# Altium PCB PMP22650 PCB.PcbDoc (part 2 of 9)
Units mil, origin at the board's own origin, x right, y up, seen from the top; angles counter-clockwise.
Board outline 11311 x 5233 mil, 8 copper layers (Layer 1, Layer 2, Layer 3, Layer 4, Layer 5, Layer 6, Layer 7, Layer 8), stack 88.6 mil thick; 633 components, 410 nets, 2503 pads, 1993 vias.
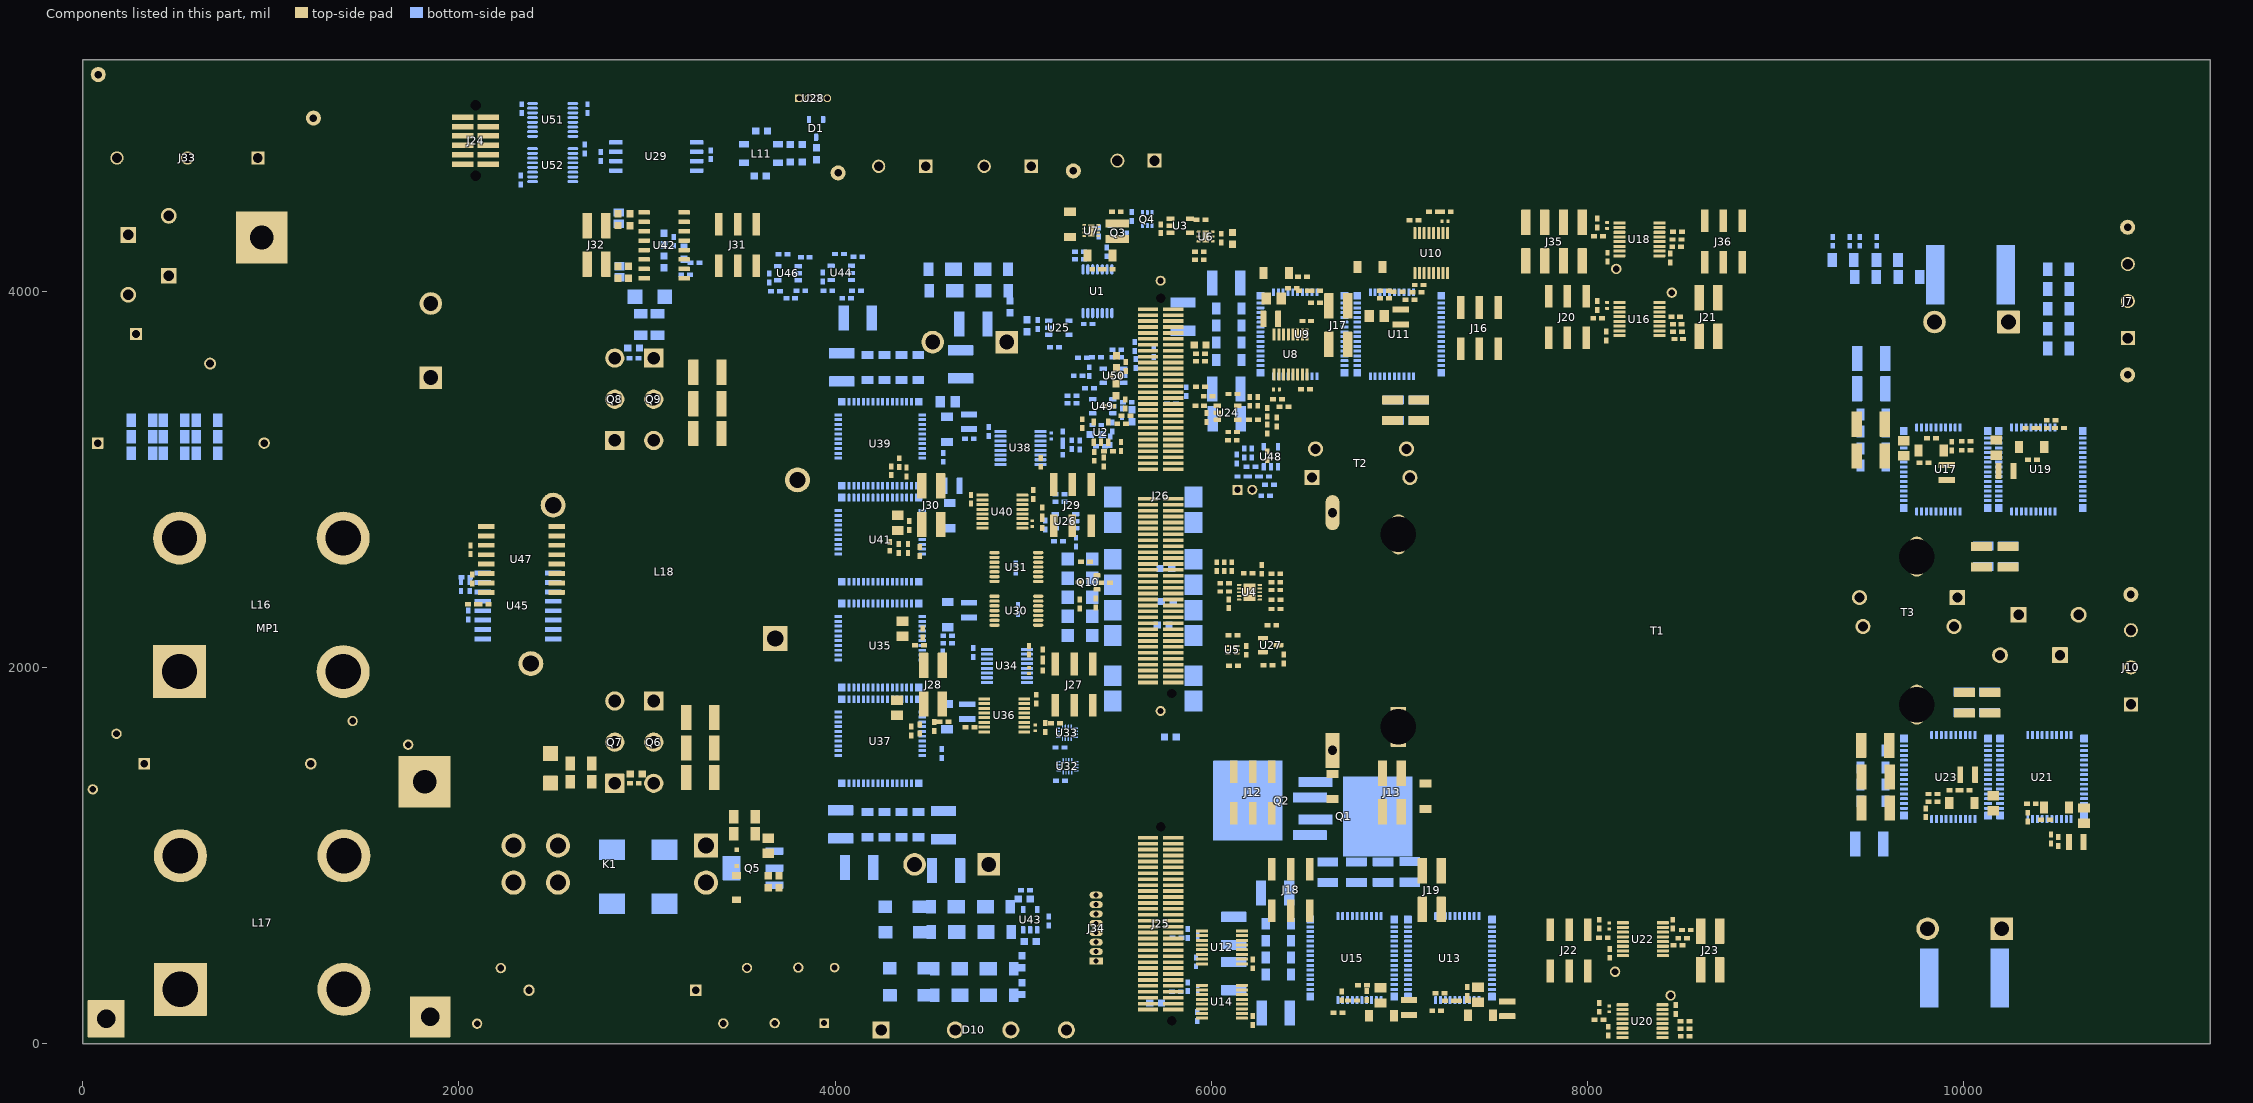
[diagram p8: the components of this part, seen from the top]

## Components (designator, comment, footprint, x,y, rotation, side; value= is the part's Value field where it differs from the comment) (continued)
R3 "WSL12066L000FEA18" 1206 10503.12,3908.46 r0 bottom value=0.006
R4 "WSL12066L000FEA18" 1206 10503.12,4014.03 r0 bottom value=0.006
R5 "WSL12066L000FEA18" 1206 10503.12,4119.6 r0 bottom value=0.006
R6 "CRCW04025K11FKED" 0402 5452.58,3151.29 r0 top value=5.11k
R7 "RMCF0402JT10R0" 0402 5376.58,3124.29 r270 top value=10.0
R8 "CRCW04025K11FKED" 0402 5519.58,3177.29 r90 top value=5.11k
R9 "ERJ-2GE0R00X" 0402 6343.27,2362.6 r0 top value=0
R10 "ERJPA2F1002X" 0402 6070.85,2405.46 r0 top value=10.0k
R11 "ERJPA2F1002X" 0402 6343.27,2312.6 r180 top value=10.0k
R12 "ERJPA2F1002X" 0402 5402.2,4317.24 r270 bottom value=10.0k
R13 "ERJPA2F1002X" 0402 6068.27,2537.6 r90 top value=10.0k
R14 "ERJPA2F1002X" 0402 6266.85,2523.46 r90 top value=10.0k
R15 "ERJPA2F1002X" 0402 6028.27,2537.6 r90 top value=10.0k
R16 "CRCW04021K00FKED" 0402 5442.9,4211.6 r90 bottom value=1.00k
R17 "ERJPA2F1002X" 0402 5576.27,4399.6 r90 bottom value=10.0k
R18 "ERJPA2F1002X" 0402 6342.85,2413.46 r0 top value=10.0k
R19 "ERJ-2GE0R00X" 0402 6342.85,2454.46 r0 top value=0
R20 "ERJPA2F1002X" 0402 6108.27,2537.6 r90 top value=10.0k
R21 "CRCW0402178KFKED" 0402 5390.38,4119.16 r0 top value=178k
R22 "ERJPA2F1002X" 0402 5298.27,4172.6 r180 bottom value=10.0k
R23 "CRCW0402100KDHEDP" 0402 5494.53,4424.53 r0 top value=100k
R24 "ERJ-2GE0R00X" 0402 6185.26,2093.12 r90 top value=0
R25 "CRCW0402953KFKED" 0402 5451.21,4119.16 r0 top value=953k
R26 "CRCW040269K8FKED" 0402 6489,4004 r0 top value=69.8k
R27 "ERJ-2GE0R00X" 0402 6555,4004 r0 top value=0
R28 "CRCW040210K0FKED" 0402 6352.27,3427.6 r0 top value=10.0k
R29 "CRCW0402300RJNED" 0402 6485,4078 r180 top value=300
R30 "CRCW040249R9FKED" 0402 6386,3389 r180 top value=49.9
R31 "CRCW040269K8FKED" 0402 6993,3999 r0 top value=69.8k
R32 "ERJ-2GE0R00X" 0402 7056,3957 r0 top value=0
R33 "CRCW040210K0FKED" 0402 7249.27,4425.6 r180 top value=10.0k
R34 "CRCW0402300RJNED" 0402 6921,3965 r180 top value=300
R35 "CRCW040249R9FKED" 0402 7181.69,4425.6 r0 top value=49.9
R36 "CRCW040269K8FKED" 0402 7265,230 r180 top value=69.8k
R37 "ERJ-2GE0R00X" 0402 7216,269 r180 top value=0
R38 "CRCW040210K0FKED" 0402 5874.65,587.28 r270 bottom value=10.0k
R39 "CRCW0402300RJNED" 0402 7361,279 r270 top value=300
R40 "CRCW040249R9FKED" 0402 5816.95,563.66 r0 bottom value=49.9
R41 "CRCW040269K8FKED" 0402 6750,231 r180 top value=69.8k
R42 "ERJ-2GE0R00X" 0402 6693,256 r270 top value=0
R43 "CRCW040210K0FKED" 0402 5874.65,304.17 r270 bottom value=10.0k
R44 "CRCW0402300RJNED" 0402 6803,313 r0 top value=300
R45 "CRCW040249R9FKED" 0402 5813.72,278.3 r0 bottom value=49.9
R46 "CRCW040269K8FKED" 0402 9936.45,3178.25 r90 top value=69.8k
R47 "ERJ-2GE0R00X" 0402 10013.27,3156.6 r0 top value=0
R48 "CRCW040210K0FKED" 0402 8051,3926 r270 top value=10.0k
R49 "CRCW0402300RJNED" 0402 9789,3089 r0 top value=300
R50 "CRCW040249R9FKED" 0402 8054,3859 r0 top value=49.9
R51 "CRCW040269K8FKED" 0402 10418,3275 r0 top value=69.8k
R52 "ERJ-2GE0R00X" 0402 10465,3315 r0 top value=0
R53 "CRCW040210K0FKED" 0402 8052,4364 r270 top value=10.0k
R54 "CRCW0402300RJNED" 0402 10366,3106 r180 top value=300
R55 "CRCW040249R9FKED" 0402 8058,4294 r0 top value=49.9
R56 "CRCW040269K8FKED" 0402 10435,1192 r180 top value=69.8k
R57 "ERJ-2GE0R00X" 0402 10359.27,1276.6 r180 top value=0
R58 "CRCW040210K0FKED" 0402 8063,195 r270 top value=10.0k
R59 "CRCW0402300RJNED" 0402 10464,1089 r90 top value=300
R60 "CRCW040249R9FKED" 0402 8061,129 r0 top value=49.9
R61 "CRCW040269K8FKED" 0402 9836,1329 r0 top value=69.8k
R62 "ERJ-2GE0R00X" 0402 9836.02,1287.6 r180 top value=0
R63 "CRCW040210K0FKED" 0402 8063,637 r270 top value=10.0k
R64 "CRCW0402300RJNED" 0402 9949,1348 r0 top value=300
R65 "CRCW040249R9FKED" 0402 8084,564 r0 top value=49.9
R66 "ERJPA2F1002X" 0402 6246.72,3416.94 r270 top value=10.0k
R67 "CRCW04020000Z0ED" 0402 6346.6,3306.87 r90 top value=0
R68 "CRCW040256R2FKED" 0402 5983.27,3442.6 r180 top value=56.2
R69 "CRCW04021K00FKED" 0402 6298,3269 r90 top value=1.00k
R70 "CRCW04021K00FKED" 0402 6224,3319.06 r180 top value=1.00k
R71 "ERJPA2F1002X" 0402 6204.27,3416.94 r90 top value=10.0k
R72 "CRCW04023K65FKED" 0402 6111.27,3208.6 r180 top value=3.65k
R73 "CRCW06037K15FKEA" 0603 5018.92,3818.6 r270 bottom value=7.15k
R74 "CRCW040219R6FKED" 0402 5693,3676 r270 bottom value=19.6
R75 "CRCW1206365KFKEA" 1206 4862.06,4119.6 r0 bottom value=365k
R76 "CRCW1206365KFKEA" 1206 4706.27,4119.6 r0 bottom value=365k
R77 "CRCW1206365KFKEA" 1206 4553.27,4119.6 r0 bottom value=365k
R78 "ERJPA2F1002X" 0402 5187.05,2673.07 r180 bottom value=10.0k
R79 "CRCW0402150KFKED" 0402 5195.88,2922.58 r0 bottom value=150k
R80 "CRCW040219R6FKED" 0402 5787.51,3403.86 r0 bottom value=19.6
R81 "CRCW040256R2FKED" 0402 6300.74,2014.32 r0 top value=56.2
R82 "ERJPA2F1002X" 0402 5280.27,2667.6 r90 bottom value=10.0k
R83 "CRCW0402150KFKED" 0402 5116.05,2759.07 r90 bottom value=150k
R84 "ERJ-3GEY0R00V" 0603 5703.27,217.6 r180 bottom value=0
R85 "RMCF0603ZT0R00" 0603 3602.21,4614.6 r0 bottom value=0
R86 "CRCW060360K4FKEA" 0603 3793.7,4689.6 r0 bottom value=60.4k
R87 "CRCW060360K4FKEA" 0603 3793.27,4782.6 r180 bottom value=60.4k
R88 "RMCF0603ZT0R00" 0603 3608.7,4853.6 r0 bottom value=0
R89 "ERJ-3GEY0R00V" 0603 5782.27,1631.6 r0 bottom value=0
R90 "ERJ-3GEY0R00V" 0603 5743.27,2227.6 r180 bottom value=0
R91 "CRCW06037K15FKEA" 0603 4929.27,3918.6 r270 bottom value=7.15k
R92 "ERJ-3GEY0R00V" 0603 5765,2353 r180 bottom value=0
R93 "ERJ-3GEY0R00V" 0603 5758.27,2527.6 r180 bottom value=0
R94 "CRCW1206365KFKEA" 1206 4863.27,4004.6 r0 bottom value=365k
R95 "CRCW1206365KFKEA" 1206 4713.38,4004.6 r0 bottom value=365k
R96 "CRCW1206365KFKEA" 1206 4557.27,4004.6 r0 bottom value=365k
R97 "CRCW040269K8FKED" 0402 4447.98,2118.88 r0 top value=69.8k
R98 "ERJ-2GE0R00X" 0402 4598.27,2130.02 r0 bottom value=0
R99 "CRCW040210K0FKED" 0402 5103.27,2072.7 r270 top value=10.0k
R100 "CRCW0402300RJNED" 0402 4598.27,2169.7 r180 bottom value=300
R101 "CRCW040249R9FKED" 0402 5103.27,2009.1 r90 top value=49.9
R102 "CRCW040269K8FKED" 0402 4450,1675 r270 top value=69.8k
R103 "ERJ-2GE0R00X" 0402 4404,1664 r270 top value=0
R104 "CRCW040210K0FKED" 0402 5117,1682 r90 top value=10.0k
R105 "CRCW0402300RJNED" 0402 4578,1712 r180 top value=300
R106 "CRCW040249R9FKED" 0402 5171,1706 r180 top value=49.9
R107 "CRCW040269K8FKED" 0402 4379.27,3040.6 r90 top value=69.8k
R108 "ERJ-2GE0R00X" 0402 4341.27,3090.6 r90 top value=0
R109 "CRCW040210K0FKED" 0402 5208.9,3232.48 r270 bottom value=10.0k
R110 "CRCW0402300RJNED" 0402 4713.27,3216.62 r180 bottom value=300
R111 "CRCW040249R9FKED" 0402 5208.9,3156.1 r90 bottom value=49.9
R112 "CRCW040269K8FKED" 0402 4387.23,2633.6 r90 top value=69.8k
R113 "ERJ-2GE0R00X" 0402 4337.63,2633.6 r270 top value=0
R114 "CRCW040210K0FKED" 0402 5100,2767 r90 top value=10.0k
R115 "CRCW0402300RJNED" 0402 4291,2646 r270 top value=300
R116 "CRCW040249R9FKED" 0402 5100,2828 r270 top value=49.9
R117 "CRCW12061R00FKEA" 1206 2648.27,1393.6 r0 top value=1.00
R118 "CRCW060310K0JNEA" 0603 2942.27,1435.6 r180 top value=10k
R119 "CRCW12065R11FKEA" 1206 2648.27,1491.6 r0 top value=5.11
R120 "RK73Z1ETTP" 0402 3205.27,4089.6 r180 bottom value=0
R121 "CRCW12061R00FKEA" 1206 3055.26,3824.39 r270 bottom value=1.00
R122 "CRCW060310K0JNEA" 0603 2928.27,3699.6 r0 bottom value=10k
R123 "RK73Z1ETTP" 0402 3255.27,4152.6 r180 bottom value=0
R124 "CRCW12065R11FKEA" 1206 2966.26,3824.39 r270 bottom value=5.11
R125 "CRCW06033K48FKEA" 0603 5036.62,545.6 r180 bottom value=3.48k
R126 "CRCW040216K5FKED" 0402 4061.19,3964.55 r0 bottom value=16.5k
R127 "CRCW1206365KFKEA" 1206 4568.63,594.8 r0 bottom value=365k
R128 "CRCW1206365KFKEA" 1206 4724.63,594.8 r0 bottom value=365k
R129 "CRCW1206365KFKEA" 1206 4878.63,594.8 r0 bottom value=365k
R130 "CRCW040219R6FKED" 0402 5011.62,816.6 r180 bottom value=19.6
R131 "CRCW040210K0FKED" 0402 4112.82,4004.95 r180 bottom value=10.0k
R132 "CRCW04023K48FKED" 0402 2010.65,2431.87 r270 bottom value=3.48k
R133 "CRCW040219R6FKED" 0402 4120.19,4184.55 r0 bottom value=19.6
R134 "CRCW1206365KFKEA" 1206 4566.63,728.8 r0 bottom value=365k
R135 "CRCW1206365KFKEA" 1206 4721.63,728.8 r0 bottom value=365k
R136 "CRCW1206365KFKEA" 1206 4874.63,728.8 r0 bottom value=365k
R137 "CRCW040210K0FKED" 0402 3960.69,4004.95 r0 bottom value=10.0k
R138 "CRCW040210K0FKED" 0402 2057.89,2431.87 r90 bottom value=10.0k
R139 "CRCW06033K48FKEA" 0603 5005.62,770.6 r0 bottom value=3.48k
R140 "CRCW040216K5FKED" 0402 3933.69,4077.55 r90 bottom value=16.5k
R141 "CRCW06037K15FKEA" 0603 4993.27,294.6 r90 bottom value=7.15k
R142 "CRCW1206365KFKEA" 1206 4586.62,259.6 r180 bottom value=365k
R143 "CRCW1206365KFKEA" 1206 4739.62,259.6 r180 bottom value=365k
R144 "CRCW1206365KFKEA" 1206 4892.62,258.6 r180 bottom value=365k
R145 "CRCW040216K5FKED" 0402 3763.89,3965.57 r180 bottom value=16.5k
R146 "CRCW040210K0FKED" 0402 3817.27,4003.57 r180 bottom value=10.0k
R147 "CRCW06037K15FKEA" 0603 4993.27,436.6 r90 bottom value=7.15k
R148 "CRCW040219R6FKED" 0402 3840.89,4181.57 r0 bottom value=19.6
R149 "CRCW04023K48FKED" 0402 2071,2337 r180 top value=3.48k
R150 "CRCW1206365KFKEA" 1206 4586.62,400.6 r180 bottom value=365k
R151 "CRCW1206365KFKEA" 1206 4736.62,400.6 r180 bottom value=365k
R152 "CRCW1206365KFKEA" 1206 4892.62,400.6 r180 bottom value=365k
R153 "CRCW040210K0FKED" 0402 3682.89,4002.57 r0 bottom value=10.0k
R154 "CRCW040216K5FKED" 0402 3649.89,4072.57 r90 bottom value=16.5k
R155 "CRCW040210K0FKED" 0402 2070.27,2471.6 r270 top value=10.0k
R156 "CRCW060310K0FKEA" 0603 3700.27,862.6 r90 top value=10.0k
R157 "CRCW12065R10JNEA" 1206 3517.25,1207.83 r0 top value=5.1
R158 "CRCW12065R10JNEA" 1206 3517.25,1117.83 r0 top value=5.1
R159 "CRF1206-FZ-R010ELF" FP-CRF1206-FZ-R010ELF_1206-MFG 5301.53,2171.68 r0 bottom
R160 "B59101P1080A062" FP-B59101P1080A062_SMD2-MFG 3093.27,888.6 r90 bottom value=13Ω
R161 "CRCW1206330KJNEA" 1206 660.11,3315.6 r180 bottom value=330k
R162 "CRCW1206330KJNEA" 1206 660.11,3228.58 r180 bottom value=330k
R163 "CRCW1206330KJNEA" 1206 660.11,3141.15 r180 bottom value=330k
R164 "CRF1206-FZ-R010ELF" FP-CRF1206-FZ-R010ELF_1206-MFG 5301.53,2273.37 r0 bottom
R165 "B59101P1080A062" FP-B59101P1080A062_SMD2-MFG 2813.27,888.6 r90 bottom value=13Ω
R166 "CRF1206-FZ-R010ELF" FP-CRF1206-FZ-R010ELF_1206-MFG 5301.53,2375.05 r0 bottom
R167 "CRCW1206330KJNEA" 1206 484.4,3315.6 r180 bottom value=330k
R168 "CRCW1206330KJNEA" 1206 484.4,3228.58 r180 bottom value=330k
R169 "CRCW1206330KJNEA" 1206 484.4,3141.15 r180 bottom value=330k
R170 "V20H510AUTO" FP-V20H510AUTO_RADIAL-MFG 480,3696.26 r0 top
R171 "CRF1206-FZ-R010ELF" FP-CRF1206-FZ-R010ELF_1206-MFG 5301.53,2476.73 r0 bottom
R172 "CRF1206-FZ-R010ELF" FP-CRF1206-FZ-R010ELF_1206-MFG 5301.53,2578.42 r0 bottom
R173 "CRCW1206330KJNEA" 1206 314.27,3315.6 r180 bottom value=330k
R174 "CRCW1206330KJNEA" 1206 314.27,3228.58 r180 bottom value=330k
R175 "CRCW1206330KJNEA" 1206 314.27,3141.15 r180 bottom value=330k
R176 "CRCW04020000Z0ED" 0402 5438.27,2452.6 r0 top value=0
R177 "CRCW04021K50FKED" 0402 5301.18,2338.63 r270 top value=1.50k
R178 "ERJPA2F1002X" 0402 6309,2974 r180 bottom value=10.0k
R179 "CRCW04020000Z0ED" 0402 6289,2915 r0 bottom value=0
R180 "CRCW040256R2FKED" 0402 5867,3468 r90 bottom value=56.2
R181 "CRCW0402549RFKED" 0402 6163,3017 r0 bottom value=549
R182 "CRCW0402549RFKED" 0402 6136,3110 r90 bottom value=549
R183 "ERJPA2F1002X" 0402 6211,3068 r180 bottom value=10.0k
R184 "CRCW04021K37FKED" 0402 6176,3142 r270 bottom value=1.37k
R185 "CRCW06038K45FKEA" 0603 5577.42,3339.46 r270 bottom value=8.45k
R186 "CRCW04022K55FKED" 0402 5257.96,3185.98 r270 bottom value=2.55k
R187 "CRCW04022K55FKED" 0402 5474.04,3280.35 r90 bottom value=2.55k
R188 "CRCW040211R0FKED" 0402 5553.27,3412.6 r0 bottom value=11.0
R189 "CRCW04022K55FKED" 0402 5301.18,3185.18 r270 bottom value=2.55k
R190 "CRCW04022K55FKED" 0402 5409.92,3178.98 r180 bottom value=2.55k
R191 "CRCW06038K45FKEA" 0603 5388.57,3239.55 r0 bottom value=8.45k
R192 "ERJ-8ENF1242V" 1206 9358.27,4167.6 r180 bottom value=12.4k
R193 "CRCW12062M00FKEA" 1206 9478.27,4077.6 r0 bottom value=2.00Meg
R194 "CRCW04027K15FKED" 0402 5258.87,3405.94 r0 bottom value=7.15k
R195 "CRCW04024K70JNED" 0402 5291.95,3552.31 r0 bottom value=4.7k
R196 "CRCW04024K70JNED" 0402 5351.76,3485.7 r0 bottom value=4.7k
R197 "CRCW12062M00FKEA" 1206 9593.27,4167.6 r0 bottom value=2.00Meg
R198 "CRCW040211R0FKED" 0402 5598.27,3617.6 r270 bottom value=11.0
R199 "CRCW04024K70JNED" 0402 5314.91,3649 r0 bottom value=4.7k
R200 "CRCW04024K70JNED" 0402 5389.5,3651.65 r0 bottom value=4.7k
R201 "CRCW12062M00FKEA" 1206 9708.27,4077.6 r0 bottom value=2.00Meg
R202 "CRCW04027K15FKED" 0402 5497.27,3691.83 r0 bottom value=7.15k
R203 "ERJPA2F1002X" 0402 5298.27,4212.6 r180 bottom value=10.0k
R204 "ERJ-2GE0R00X" 0402 6342.85,2499.84 r0 top value=0
R205 "CRCW04020000Z0ED" 0402 9303.27,4267.6 r90 bottom value=0
R206 "CRCW04020000Z0ED" 0402 9393.27,4267.6 r90 bottom value=0
R207 "CRCW04020000Z0ED" 0402 9448.27,4267.6 r90 bottom value=0
R208 "CRCW04020000Z0ED" 0402 9538.27,4267.6 r90 bottom value=0
R209 "CRCW040210R0JNED" 0402 8478,3787 r0 top value=10
R210 "CRCW040210R0JNED" 0402 8477,3826 r0 top value=10
R211 "CRCW040210R0JNED" 0402 8469,3866 r0 top value=10
R212 "CRCW040210R0JNED" 0402 8474,4238 r0 top value=10
R213 "CRCW040210R0JNED" 0402 8475,4277 r0 top value=10
R214 "CRCW040210R0JNED" 0402 8479,4318 r0 top value=10
R215 "CRCW040210R0JNED" 0402 8518,81 r0 top value=10
R216 "CRCW040210R0JNED" 0402 8518,121 r0 top value=10
R217 "CRCW040210R0JNED" 0402 8519,41 r0 top value=10
R218 "CRCW040210R0JNED" 0402 8506,563 r0 top value=10
R219 "CRCW040210R0JNED" 0402 8525,606 r0 top value=10
R220 "CRCW040210R0JNED" 0402 8481,524 r0 top value=10
T1 "VT-20163" FP-VT-20163_PTH_TRANSFORMER_73MM0_51MM0-MFG 8274.27,2197.6 r180 top
T2 "RLTI-1371" FP-RLTI-1371_PTH_XFRMR_0IN828_0IN300-MFG 6795.36,3087.5 r0 top
T3 "RLTI-1379" FP-RLTI-1379_PTH_XFRMR_0IN828_0IN300-MFG 9706,2296.5 r180 top
TP1 "5001" Keystone5001 10871.53,3557.35 r90 top
TP2 "5001" Keystone5001 10871.53,4342.19 r90 top
TP3 "5000" Keystone5000 10888.27,2389.6 r90 top
TP5 "5001" Keystone5001 5266,4642 r90 top
TP6 "5001" Keystone5001 1226.27,4922.6 r90 top
TP7 "5000" Keystone5000 82,5154 r90 top
TP8 "5000" Keystone5000 4016,4631 r90 top
U1 "SN74HC21QPWRG4Q1" PW0014A_N 5394.44,4001.86 r270 bottom
U2 "TLV314QDBVRQ1" DBV0005A_N 5413.27,3252.6 r90 top
U3 "REF4132B33DBVRQ1" DBV0005A-MFG 5834.52,4350.97 r0 top
U4 "TPS3850G12QDRCRQ1" DRC0010R 6202.75,2401.6 r0 top
U5 "TPS3703A4330DSERQ1" DSE0006A 6111.82,2095.29 r0 top
U6 "TPS74533PQWDRVRQ1" DRV0006C-MFG 5969.45,4292.91 r180 top
U7 "TPS62170QDSGRQ1" DSG0008A 5360.87,4324.44 r0 top
U8 "ISO7741FQDBQRQ1" DBQ0016A-MFG#1 6421.48,3666.04 r270 top
U9 "LMG3525R030Q" RQS0052A-MFG 6484.47,3773.29 r180 bottom
U10 "ISO7741FQDBQRQ1" DBQ0016A-MFG#1 7169.19,4204.6 r90 top
U11 "LMG3525R030Q" RQS0052A-MFG 6999.12,3773.29 r180 bottom
U12 "ISO7741FQDBQRQ1" DBQ0016A-MFG#1 6056.27,513.55 r180 top
U13 "LMG3525R030Q" RQS0052A-MFG 7268.67,456.72 r0 bottom
U14 "ISO7741FQDBQRQ1" DBQ0016A-MFG#1 6056.27,224.55 r180 top
U15 "LMG3525R030Q" RQS0052A-MFG 6748.67,456.72 r0 bottom
U16 "ISO7741FQDBQRQ1" DBQ0016A-MFG#1 8276,3854 r180 top
U17 "LMG3525R030Q" RQS0052A-MFG 9904.27,3054.6 r180 bottom
U18 "ISO7741FQDBQRQ1" DBQ0016A-MFG#1 8276,4278 r180 top
U19 "LMG3525R030Q" RQS0052A-MFG 10409.27,3054.6 r180 bottom
U20 "ISO7741FQDBQRQ1" DBQ0016A-MFG#1 8292,121 r180 top
U21 "LMG3525R030Q" RQS0052A-MFG 10416.69,1419.28 r0 bottom
U22 "ISO7741FQDBQRQ1" DBQ0016A-MFG#1 8294,557 r180 top
U23 "LMG3525R030Q" RQS0052A-MFG 9905.84,1419.28 r0 bottom
U24 "OPA365AQDBVRQ1" DBV0005A_N 6086.49,3356.46 r0 top
U25 "OPA320AQDBVRQ1" DBV0005A_N 5188.92,3808.6 r0 bottom
U26 "LMV796QMF/NOPB" DBV0005A_N 5224.05,2780.07 r180 bottom
U27 "TMP235AEDBZTQ1" DBZ0003A-MFG 6315.74,2120.32 r0 top
U28 "GRPB041VWVN-RC" Sullins_GRPB041VWVN-RC 3883.27,5027.6 r0 top
U29 "ISO1042BQDWVRQ1" DWV0008A-MFG 3048.7,4718.6 r0 bottom
U30 "SN74HC21QPWRG4Q1" PW0014A_N 4963.27,2303.57 r0 top
U31 "SN74AHCT08QPWRG4Q1" PW0014A_N 4963.27,2535.57 r0 top
U32 "TMUX1208QRSVRQ1" RSV0016A-MFG 5235.03,1476.48 r270 bottom
U33 "TMUX1208QRSVRQ1" RSV0016A-MFG 5232.17,1654.2 r270 bottom
U34 "ISO7741FQDBQRQ1" DBQ0016A-MFG#2 4913.27,2009.6 r0 bottom
U35 "LMG3525R030Q" RQS0052A-MFG 4239.69,2118.29 r90 bottom
U36 "ISO7741FQDBQRQ1" DBQ0016A-MFG#2 4899,1747 r0 top
U37 "LMG3525R030Q" RQS0052A-MFG 4239.69,1609.87 r90 bottom
U38 "ISO7741FQDBQRQ1" DBQ0016A-MFG#2 4985.27,3168.6 r0 bottom
U39 "LMG3525R030Q" RQS0052A-MFG 4239.69,3190.78 r90 bottom
U40 "ISO7741FQDBQRQ1" DBQ0016A-MFG#2 4889,2830 r0 top
U41 "LMG3525R030Q" RQS0052A-MFG 4239.69,2681.2 r90 bottom
U42 "UCC21222QDRQ1" D0016B-MFG 3090.3,4246 r180 top
U43 "OPA320AQDBVRQ1" DBV0005A_N 5036.62,660.6 r90 bottom
U44 "OPA320AQDBVRQ1" DBV0005A_N 4032.48,4099.03 r180 bottom
U45 "ACS733KLATR-40AB-T" FP-ACS733KLATR-40AB-T_SOIC16-MFG 2313.27,2328.6 r180 bottom
U46 "OPA320AQDBVRQ1" DBV0005A_N 3749.18,4097.57 r180 bottom
U47 "ACS733KLATR-40AB-T" FP-ACS733KLATR-40AB-T_SOIC16-MFG 2332,2576 r180 top
U48 "OPA365AQDBVRQ1" DBV0005A_N 6317,3122 r90 bottom
U49 "OPA320AQDBVRQ1" DBV0005A_N 5422.65,3390.6 r180 bottom
U50 "OPA320AQDBVRQ1" DBV0005A_N 5480.16,3552.31 r180 bottom
U51 "ISO7761DBQR" DBQ0016A_N 2498.27,4912.6 r0 bottom
U52 "ISO7730DBQR" DBQ0016A_N 2498.27,4672.6 r180 bottom
ZZ1 "These assemblies must comply with workmanship standards IPC-A-610 Class 2, unless otherwise specified." AssemblyNote 158,5598 r0 top
ZZ2 "These assemblies must be clean and free from flux and all contaminants. Use of no clean flux is not acceptable." AssemblyNote 168,5492.71 r0 top
ZZ3 "These assemblies are ESD sensitive, ESD precautions shall be observed." AssemblyNote 168,5392.43 r0 top
ZZ4 "This Assembly Note is for PCB labels only" AssemblyNoteLabel 168,5297.14 r0 top

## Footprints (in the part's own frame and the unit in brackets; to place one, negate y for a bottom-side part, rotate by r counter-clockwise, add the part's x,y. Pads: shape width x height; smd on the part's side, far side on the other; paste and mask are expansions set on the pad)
0-MFG [mm]
  rrect1% 7x7 / inner round 5.08 / far side rrect1% 7x7 hole 3.2 paste-1000 mask+0: 1(-1.5,52.75) 2(20.5,-20.75)
  rrect2% 5.5x5.5 / inner round 4.318 / far side rrect2% 5.5x5.5 hole 2.5 paste-1000 mask+0: 3(21.25,-52.5)
  rrect2% 5x5 / inner round 4.318 / far side rrect2% 5x5 hole 2.5 paste-1000 mask+0: 4(-22.5,-52.75)
  silkscreen extent -25,-56.28 25,57.6, body extent -25.1,-56.35 25.1,56.35, height 0.25
0402 [mm] "0402 from SM-752 data"
  rect 0.8x0.6 smd: 1(-0.6,0) 2(0.6,0)
  silkscreen extent -1.22,-0.52 1.22,0.52, body extent -0.55,-0.3 0.55,0.3, height 0.6
0603 [mm] "0603 from SM-752 data"
  rect 1x0.95 smd: 1(-0.8,0) 2(0.8,0)
  silkscreen extent -1.52,-0.69 1.52,0.69, body extent -0.87,-0.47 0.87,0.47, height 1
0805_HV [mil] "0805 with 30mil clearance between pads"
  rect 50x63 smd: 1(-40,0) 2(40,0)
  silkscreen extent -74,-40 74,40, body extent -43,-29 43,29, height 57
0805L [mm] "0805 from SM-752 data"
  rect 1.1x1.4 smd: 1(-0.75,0) 2(0.75,0)
  body extent -1.1,-0.72 1.1,0.72, height 1.45
1206 [mm] "1206 from SM-752 data"
  rect 1.3x1.85 smd: 1(-1.45,0) 2(1.45,0)
  silkscreen extent -2.4,-1.21 2.4,1.21, body extent -1.7,-0.9 1.7,0.9, height 1.35
1206_180 [mm] "1206_180"
  rect 1.1x1.6 smd: 1(-1.7,0) 2(1.7,0)
  silkscreen extent -0.9,-1 0.9,1, body extent -1.75,-0.95 1.75,0.95, height 1.8
1206_190 [mm] "1206_190"
  rect 1.1x1.6 smd: 1(-1.7,0) 2(1.7,0)
  silkscreen extent -0.9,-1 0.9,1, body extent -1.75,-0.95 1.75,0.95, height 1.9
ACT45B [mm] "SMD, 4-Leads, Body 4.7 x 3.7 mm"
  rect 1.35x0.9 smd: 1(-2.275,1.25) 2(-2.275,-1.25) 3(2.275,-1.25) 4(2.275,1.25)
  silkscreen extent -2.35,-1.7 2.35,2, body extent -2.35,-1.7 2.35,1.7, height 3
AssemblyNote [mil] "Assembly Note"
AssemblyNoteLabel [mil] "Assembly Note for PCB Labels"
AY2_950x500_Straight [mm] "TH, 2-Leads, 9.5x5mm, Pin Spacing 7.5mm"
  round 1.4 hole 0.9: 1(-3.75,1.6) 2(3.75,-1.6)
  silkscreen extent -4.75,-2.5 4.75,2.5, body extent -4.74,-2.5 4.75,2.5, height 12.5
AY2_1300x500_Straight [mm] "TH, 2-Leads, 11x5mm, Pin Spacing 7.5mm"
  round 1.4 hole 0.9: 1(-3.75,1.6) 2(3.75,-1.6)
  silkscreen extent -6.5,-2.5 6.5,2.5, body extent -6.5,-2.5 6.5,2.5, height 16
B58031I_1084x785x450 [mm] "SMD, 2-Leads, Body 6.84x7.85mm"
  rect 2.5x8 smd: 1(-4.75,0) 2(4.75,0)
  silkscreen extent -3.2,-3.92 3.2,3.93, body extent -5.67,-4.17 5.67,4.18, height 4.5
CE_Mark_5mm [mil] "Minimum text height for CE Mark"
  silkscreen extent -138,-98 138,98
controlCARD-120HSEC [mm] "Pads are not numbered according to Samtec datasheet."
  rect 0.5x2.724 smd: 1(-23.357,-1.678) 2(-23.357,1.722) 3(-22.557,-1.678) 4(-22.557,1.722) 5(-21.757,-1.678) 6(-21.757,1.722) 7(-20.957,-1.678) 8(-20.957,1.722) 9(-20.157,-1.678) 10(-20.157,1.722) 11(-19.357,-1.678) 12(-19.357,1.722) 13(-18.557,-1.678) 14(-18.557,1.722) 15(-17.757,-1.678) 16(-17.757,1.722) 17(-16.957,-1.678) 18(-16.957,1.722) 19(-16.157,-1.678) 20(-16.157,1.722) 21(-15.357,-1.678) 22(-15.357,1.722) 23(-14.557,-1.678) 24(-14.557,1.722) 25(-13.757,-1.678) 26(-13.757,1.722) 27(-12.957,-1.678) 28(-12.957,1.722) 29(-12.157,-1.678) 30(-12.157,1.722) 31(-11.357,-1.678) 32(-11.357,1.722) 33(-10.557,-1.678) 34(-10.557,1.722) 35(-9.757,-1.678) 36(-9.757,1.722) 37(-8.957,-1.678) 38(-8.957,1.722) 39(-8.157,-1.678) 40(-8.157,1.722) 41(-7.357,-1.678) 42(-7.357,1.722) 43(-6.557,-1.678) 44(-6.557,1.722) 45(-5.757,-1.678) 46(-5.757,1.722) 47(-4.957,-1.678) 48(-4.957,1.722) 49(-4.157,-1.678) 50(-4.157,1.722) 51(-3.357,-1.678) 52(-3.357,1.722) 53(-2.557,-1.678) 54(-2.557,1.722) 55(-1.757,-1.678) 56(-1.757,1.722) 57(2.243,-1.678) 58(2.243,1.722) 59(3.043,-1.678) 60(3.043,1.722) 61(3.843,-1.678) 62(3.843,1.722) 63(4.643,-1.678) 64(4.643,1.722) 65(5.443,-1.678) 66(5.443,1.722) 67(6.243,-1.678) 68(6.243,1.722) 69(7.043,-1.678) 70(7.043,1.722) 71(7.843,-1.678) 72(7.843,1.722) 73(8.643,-1.678) 74(8.643,1.722) 75(9.443,-1.678) 76(9.443,1.722) 77(10.243,-1.678) 78(10.243,1.722) 79(11.043,-1.678) 80(11.043,1.722) 81(11.843,-1.678) 82(11.843,1.722) 83(12.643,-1.678) 84(12.643,1.722) 85(13.443,-1.678) 86(13.443,1.722) 87(14.243,-1.678) 88(14.243,1.722) 89(15.043,-1.678) 90(15.043,1.722) 91(15.843,-1.678) 92(15.843,1.722) 93(16.643,-1.678) 94(16.643,1.722) 95(17.443,-1.678) 96(17.443,1.722) 97(18.243,-1.678) 98(18.243,1.722) 99(19.043,-1.678) 100(19.043,1.722) 101(19.843,-1.678) 102(19.843,1.722) 103(20.643,-1.678) 104(20.643,1.722) 105(21.443,-1.678) 106(21.443,1.722) 107(22.243,-1.678) 108(22.243,1.722) 109(23.043,-1.678) 110(23.043,1.722) 111(23.843,-1.678) 112(23.843,1.722) 113(24.643,-1.678) 114(24.643,1.722) 115(25.443,-1.678) 116(25.443,1.722) 117(26.243,-1.678) 118(26.243,1.722) 119(27.043,-1.678) 120(27.043,1.722)
  round 0.025 hole 1.27 unplated mask+0.876: 181(-24.857,0.022) 182(28.543,1.522)
  round 1.348 hole 0.84: 185(-27.207,0.022) 186(30.893,0.022)
  silkscreen extent -32.11,-3.86 35.8,3.9, body extent -31.75,-3.48 35.3,3.52, height 12.35
controlCARD-180HSEC-60pinAddon [mm] "Pads are not numbered according to datasheet."
  round 0.025 hole 1.27 unplated mask+0.876: 61(-13.1,0) 62(13.1,1.5)
  rect 0.5x2.724 smd: 121(-11.6,-1.7) 122(-11.6,1.7) 123(-10.8,-1.7) 124(-10.8,1.7) 125(-10,-1.7) 126(-10,1.7) 127(-9.2,-1.7) 128(-9.2,1.7) 129(-8.4,-1.7) 130(-8.4,1.7) 131(-7.6,-1.7) 132(-7.6,1.7) 133(-6.8,-1.7) 134(-6.8,1.7) 135(-6,-1.7) 136(-6,1.7) 137(-5.2,-1.7) 138(-5.2,1.7) 139(-4.4,-1.7) 140(-4.4,1.7) 141(-3.6,-1.7) 142(-3.6,1.7) 143(-2.8,-1.7) 144(-2.8,1.7) 145(-2,-1.7) 146(-2,1.7) 147(-1.2,-1.7) 148(-1.2,1.7) 149(-0.4,-1.7) 150(-0.4,1.7) 151(0.4,-1.7) 152(0.4,1.7) 153(1.2,-1.7) 154(1.2,1.7) 155(2,-1.7) 156(2,1.7) 157(2.8,-1.7) 158(2.8,1.7) 159(3.6,-1.7) 160(3.6,1.7) 161(4.4,-1.7) 162(4.4,1.7) 163(5.2,-1.7) 164(5.2,1.7) 165(6,-1.7) 166(6,1.7) 167(6.8,-1.7) 168(6.8,1.7) 169(7.6,-1.7) 170(7.6,1.7) 171(8.4,-1.7) 172(8.4,1.7) 173(9.2,-1.7) 174(9.2,1.7) 175(10,-1.7) 176(10,1.7) 177(10.8,-1.7) 178(10.8,1.7) 179(11.6,-1.7) 180(11.6,1.7)
  silkscreen extent -14.68,-3.88 14.68,3.88, body extent -14.3,-3.5 14.3,3.5, height 7.95
D0016B-MFG [mm]
  rrect17% 1.55x0.6 smd: 1(-2.7,4.445) 2(-2.7,3.175) 3(-2.7,1.905) 4(-2.7,0.635) 5(-2.7,-0.635) 6(-2.7,-1.905) 7(-2.7,-3.175) 8(-2.7,-4.445) 9(2.7,-4.445) 10(2.7,-3.175) 11(2.7,-1.905) 12(2.7,-0.635) 13(2.7,0.635) 14(2.7,1.905) 15(2.7,3.175) 16(2.7,4.445)
  silkscreen extent -4.18,-5 1.55,5, body extent -3.57,-5.25 3.57,5.25, height 0.25
DBQ0016A-MFG#1 [mm]
  rrect24% 1.6x0.41 smd paste+0 mask+0: 1(-2.7,2.222) 2(-2.7,1.587) 3(-2.7,0.952) 4(-2.7,0.317) 5(-2.7,-0.318) 6(-2.7,-0.953) 7(-2.7,-1.588) 8(-2.7,-2.223) 9(2.7,-2.222) 10(2.7,-1.587) 11(2.7,-0.952) 12(2.7,-0.317) 13(2.7,0.318) 14(2.7,0.953) 15(2.7,1.588) 16(2.7,2.223)
  silkscreen extent -4.17,-2.5 1.5,2.5, body extent -3.6,-2.75 3.6,2.75, height 0.25
DBQ0016A-MFG#2 [mm]
  rrect24% 1.6x0.41 smd: 1(-2.7,2.222) 2(-2.7,1.587) 3(-2.7,0.953) 4(-2.7,0.318) 5(-2.7,-0.318) 6(-2.7,-0.953) 7(-2.7,-1.587) 8(-2.7,-2.222) 9(2.7,-2.222) 10(2.7,-1.587) 11(2.7,-0.953) 12(2.7,-0.318) 13(2.7,0.318) 14(2.7,0.953) 15(2.7,1.587) 16(2.7,2.222)
  silkscreen extent -4.17,-2.5 1.5,2.5, body extent -3,-2.45 3,2.45, height 1.75
DBQ0016A_N [mm] "SOP, 16-Leads, Body 4.9x3.9mm, Pitch 0.635mm, IPC Medium Density"
  oval 1.45x0.4 smd: 1(-2.725,2.222) 2(-2.725,1.587) 3(-2.725,0.953) 4(-2.725,0.318) 5(-2.725,-0.318) 6(-2.725,-0.953) 7(-2.725,-1.587) 8(-2.725,-2.222) 9(2.725,-2.222) 10(2.725,-1.587) 11(2.725,-0.953) 12(2.725,-0.318) 13(2.725,0.318) 14(2.725,0.953) 15(2.725,1.587) 16(2.725,2.222)
  silkscreen extent -3.35,-2.5 1.1,2.68, body extent -3.01,-2.45 3.01,2.45, height 1.63
DBV0005A-MFG [mm]
  rrect17% 1.1x0.6 smd paste+0 mask+0: 1(-1.3,0.95) 2(-1.3,0) 3(-1.3,-0.95) 4(1.3,-0.95) 5(1.3,0.95)
  silkscreen extent -2.57,-1.53 0.87,1.53, body extent -1.95,-1.78 1.95,1.78, height 0.25
DBV0005A_N [mm] "SOT23, 5-Leads, Body 2.9x1.6mm, Pitch 0.95mm, Lead Span 2.8mm, IPC Medium Density"
  rrect17% 1x0.6 smd: 1(-1.375,0.95) 2(-1.375,0) 3(-1.375,-0.95) 4(1.375,-0.95) 5(1.375,0.95)
  silkscreen extent -0.25,-1.55 0.25,1.55, body extent -1.42,-1.46 1.42,1.46, height 1.09
DBZ0003A-MFG [mm]
  rrect17% 1.3x0.6 smd paste+0 mask+0: 1(-1.05,0.95) 2(-1.05,-0.95) 3(1.05,0)
  silkscreen extent -0.7,-1.52 0.7,1.52, body extent -1.8,-1.62 1.8,1.62, height 0.25
DRC0010R [mm] "VSON-10"
  rrect40% 0.6x0.25 smd: 1(-1.4,1) 2(-1.4,0.5) 3(-1.4,0) 4(-1.4,-0.5) 5(-1.4,-1) 6(1.4,-1) 7(1.4,-0.5) 8(1.4,0) 9(1.4,0.5) 10(1.4,1)
  rrect12% 1.65x2.4 smd paste-1 mask-2: 11(0,0)
  Layer 1 region: -0.375,-1.65 -0.375,-1.2 -0.775,-1.2 -0.794,-1.196 -0.81,-1.185 -0.821,-1.169 -0.825,-1.15 -0.825,-1.15 -0.825,1.15 -0.821,1.169 -0.81,1.185 -0.794,1.196 -0.775,1.2 -0.775,1.2 -0.375,1.2 -0.375,1.65 -0.371,1.669 -0.36,1.685 -0.344,1.696 -0.325,1.7 -0.325,1.7 -0.325,1.7 -0.175,1.7 -0.175,1.7 -0.156,1.696 -0.14,1.685 -0.129,1.669 -0.125,1.65 -0.125,1.65 -0.125,1.2 0.125,1.2 0.125,1.65 0.129,1.669 0.14,1.685 0.156,1.696 0.175,1.7 0.175,1.7 0.175,1.7 0.325,1.7 0.325,1.7 0.344,1.696 0.36,1.685 0.371,1.669 0.375,1.65 0.375,1.65 0.375,1.2 0.775,1.2 0.794,1.196 0.81,1.185 0.821,1.169 0.825,1.15 0.825,1.15 0.825,-1.15 0.821,-1.169 0.81,-1.185 0.794,-1.196 0.775,-1.2 0.775,-1.2 0.375,-1.2 0.375,-1.65 0.371,-1.669 0.36,-1.685 0.344,-1.696 0.325,-1.7 0.325,-1.7 0.175,-1.7 0.156,-1.696 0.14,-1.685 0.129,-1.669 0.125,-1.65 0.125,-1.65 0.125,-1.2 -0.125,-1.2 -0.125,-1.65 -0.129,-1.669 -0.14,-1.685 -0.156,-1.696 -0.175,-1.7 -0.175,-1.7 -0.325,-1.7 -0.344,-1.696 -0.36,-1.685 -0.371,-1.669 -0.375,-1.65
  silkscreen extent -1.65,-1.65 1.65,1.65, body extent -1.5,-1.5 1.5,1.5, height 0.87
DRV0006C-MFG [mm]
  rrect33% 0.5x0.3 smd paste+0 mask+0: 1(-0.95,0.65) 2(-0.95,0) 3(-0.95,-0.65) 4(0.95,-0.65) 5(0.95,0) 6(0.95,0.65)
  rrect11% 0.9x1.6 smd paste-1000 mask+0: 7(0,0)
  silkscreen extent -1.88,-1.15 1,1.15, body extent -1.3,-1.15 1.3,1.15, height 0.25
DSE0006A [mm] "TI recommended land pattern"
  rect 0.66x0.25 smd: 1(-0.62,0.5)
  rect 0.7x0.25 smd: 2(-0.6,0) 3(-0.6,-0.5) 4(0.6,-0.5) 5(0.6,0) 6(0.6,0.5)
  Layer 1 region: -0.3,0.625 -0.25,0.625 -0.15,0.525 -0.15,0.375 -0.3,0.375
  silkscreen extent -0.9,-0.92 0.9,0.92, body extent -0.77,-0.77 0.77,0.77, height 0.8
DSG0008A [mm] "SON, 8-Leads, Body 2x2mm, Pitch 0.5mm, Thermal Pad 1.6x0.9mm, TI Recommended"
  rrect40% 0.5x0.25 smd: 1(-0.95,0.75) 2(-0.95,0.25) 3(-0.95,-0.25) 4(-0.95,-0.75) 5(0.95,-0.75) 6(0.95,-0.25) 7(0.95,0.25) 8(0.95,0.75)
  rrect14% 0.9x0.7 on Top Paste: 9(0,-0.45) 9(0,0.45)
  rrect11% 0.9x1.6 smd paste-0.45: 9(0,0)
  silkscreen extent -1.07,-1.15 1.07,1.15, body extent -1,-1 1,1, height 0.77
DWV0008A-MFG [mm]
  rrect17% 1.8x0.6 smd: 1(-5.45,1.905) 2(-5.45,0.635) 3(-5.45,-0.635) 4(-5.45,-1.905) 5(5.45,-1.905) 6(5.45,-0.635) 7(5.45,0.635) 8(5.45,1.905)
  silkscreen extent -7.1,-2.98 3.8,2.98, body extent -5.75,-2.93 5.75,2.93, height 2.8
FCC_disclaimer [mil]
FP-292161-2_HDR2-MFG [mm]
  rrect7% 1.35x1.35 hole 0.85 paste-1000 mask+0: 1(-1.3,0.2)
  round 1.35 hole 0.85 paste-1000 mask+0: 2(0.7,0.2)
  silkscreen extent -3,-1.9 3,1.9, body extent -3.1,-2 3.1,2, height 0.25
FP-0525025.MXEP_vm_AXIAL-MFG [mm]
  rrect5% 2.15x2.15 hole 1.4 paste-1000 mask+0: 1(0,0)
  round 2.15 hole 1.4 paste-1000 mask+0: 2(8.092,0)
  silkscreen extent -3.64,-3.64 3.64,3.64, body extent -3.74,-3.74 9.27,3.74, height 0.25
FP-ACS733KLATR-40AB-T_SOIC16-MFG [mm]
  rrect15% 2.25x0.65 smd paste+0 mask+0: 1(-4.75,4.445) 2(-4.75,3.175) 3(-4.75,1.905) 4(-4.75,0.635) 5(-4.75,-0.635) 6(-4.75,-1.905) 7(-4.75,-3.175) 8(-4.75,-4.445) 9(4.75,-4.445) 10(4.75,-3.175) 11(4.75,-1.905) 12(4.75,-0.635) 13(4.75,0.635) 14(4.75,1.905) 15(4.75,3.175) 16(4.75,4.445)
  silkscreen extent -6.55,-5.25 3,5.25, body extent -5.15,-5.15 5.15,5.15, height 2.65
FP-ALA7DA471DE500_RADIAL-MFG [mm]
  rrect3% 3.05x3.05 hole 2 paste-1000 mask+0: 1(-5,0)
  round 3.05 hole 2 paste-1000 mask+0: 2(5,0)
  silkscreen extent -18,-18 18,18, body extent -18.1,-18.1 18.1,18.1, height 0.25
FP-ALA8DA301CF500_RADIAL-MFG [mm]
  rrect3% 3.05x3.05 hole 2 paste-1000 mask+0: 1(-5,0)
  round 3.05 hole 2 paste-1000 mask+0: 2(5,0)
  silkscreen extent -15.5,-15.5 15.5,15.5, body extent -15.6,-15.6 15.6,15.6, height 0.25
FP-AY2101K29Y5SS63L7_RADIAL-MFG [mm]
  rrect8% 1.3x1.3 hole 0.8 paste-1000 mask+0: 1(-3.75,0.7)
  round 1.3 hole 0.8 paste-1000 mask+0: 2(3.75,-0.7)
  silkscreen extent -6.5,-2.5 6.5,2.5, body extent -6.6,-2.6 6.6,2.6, height 0.25
FP-B32923H3225M000_RADIAL-MFG [mm]
  rrect6% 1.55x1.55 hole 1 paste-1000 mask+0: 1(-11.25,0)
  round 1.55 hole 1 paste-1000 mask+0: 2(11.25,0)
  silkscreen extent -13.25,-7.25 13.25,7.25, body extent -13.35,-7.35 13.35,7.35, height 0.25
FP-B59101P1080A062_SMD2-MFG [mm]
  rrect4% 2.8x3.5 smd paste+0 mask+0: 1(-3.65,0) 2(3.65,0)
  silkscreen extent -4.25,-3.4 4.25,3.4, body extent -4,-3.15 4,3.15, height 3.8
FP-C1210X333JBGACAUTO_1210-MFG [mm]
  rrect8% 1.22x2.81 smd paste+0 mask+0: 1(-1.39,0) 2(1.39,0)
  silkscreen extent -0.41,-1.45 0.41,1.45, body extent -1.65,-1.3 1.65,1.3, height 2.8
FP-C1812X104KDRACAUTO_1812-MFG#1 [mm]
  rrect7% 1.4x3.4 smd paste+0 mask+0: 1(-1.9,0) 2(1.9,0)
  silkscreen extent -0.82,-1.75 0.82,1.75, body extent -2.25,-1.6 2.25,1.6, height 1.85
FP-C1812X104KDRACAUTO_1812-MFG#2 [mm]
  rrect7% 1.4x3.4 smd: 1(-1.9,0) 2(1.9,0)
  silkscreen extent -0.82,-1.75 0.82,1.75, body extent -2.25,-1.6 2.25,1.6, height 1.85
FP-CRF1206-FZ-R010ELF_1206-MFG [mm]
  rrect6% 1.7x1.8 smd paste+0 mask+0: 1(-1.65,0) 2(1.65,0)
  silkscreen extent -0.43,-0.92 0.43,0.92, body extent -1.6,-0.82 1.6,0.82, height 0.8
FP-FRM-DOC-15_Common_Mode_Choke_1INCH90_1INCH9-MFG [mm]
  rrect1% 7.15x7.15 hole 4.75 paste-1000 mask+0: 1(-11.049,-9.017)
  round 7.15 hole 4.75 paste-1000 mask+0: 2(11.049,-9.017) 3(11.049,9.017) 4(-11.049,9.017)
  silkscreen extent -24.85,-13.97 24.13,13.97, body extent -24.23,-14.07 24.23,14.07, height 0.25
FP-FTR-K5AA012Y_RELAY_PTH-MFG [mm]
  rrect3% 3.25x3.25 hole 2.15 paste-1000 mask+0: 1(-13.05,-2.5)
  round 3.25 hole 2.15 paste-1000 mask+0: 2(-13.05,2.5) 3(6.95,-2.5) 3(6.95,2.5) 4(12.95,-2.5) 4(12.95,2.5)
  silkscreen extent -16.13,-9.15 15.4,9.15, body extent -15.25,-9 15.25,9, height 30
FP-GCM1555C1H680JA16D_0402-MFG#1 [mm]
  rrect25% 0.4x0.5 smd paste+0 mask+0: 1(-0.4,0) 2(0.4,0)
  silkscreen extent -0.53,-0.63 0.53,0.63, body extent -0.7,-0.38 0.7,0.38, height 0.25
FP-GCM1555C1H680JA16D_0402-MFG#2 [mm]
  rrect25% 0.4x0.5 smd: 1(-0.4,0) 2(0.4,0)
  silkscreen extent -0.53,-0.63 0.53,0.63, body extent -0.7,-0.38 0.7,0.38, height 0.25
FP-IPB80R290C3AATMA2_D2PAK-MFG [mm]
  rrect7% 1.35x4.6 smd paste-1000 mask+0: 1(-2.54,-5.775) 3(2.54,-5.775)
  rrect1% 10.8x9.4 smd paste-1000 mask+0: 2(0,3.375)
  silkscreen extent -5.1,-2.73 5.1,-1.7, body extent -5,-7.64 5,7.65, height 4.7
FP-MPIA2510V2-4R7-R_1008-MFG#1 [mm]
  rrect13% 0.8x2.2 smd paste+0 mask+0: 1(-1,0) 2(1,0)
  silkscreen extent -0.23,-1.1 0.23,1.1, body extent -1.5,-1.2 1.5,1.2, height 0.25
FP-MPIA2510V2-4R7-R_1008-MFG#2 [mm]
  rrect13% 0.8x2.2 smd: 1(-1,0) 2(1,0)
  silkscreen extent -0.23,-1.1 0.23,1.1, body extent -1.25,-1 1.25,1, height 1.05
FP-NRVBA340T3G_SMA-MFG [mm]
  rrect5% 2x2 smd: 1(-2,0) 2(2,0)
  silkscreen extent -4.3,-1.46 2.28,1.46, body extent -2.61,-1.3 2.61,1.3, height 2.2
FP-NVHL025N65S3_hm_TO-247-3-MFG [mm]
  rrect4% 2.6x2.6 hole 1.7 paste-1000 mask+0: 1(5.56,-12.323)
  round 2.6 hole 1.7 paste-1000 mask+0: 2(0,-12.323) 3(-5.56,-12.323)
  silkscreen extent -7.94,-14.32 7.94,10.41, body extent -7.81,-12.63 7.81,10.28, height 4.82
FP-RLTI-1371_PTH_XFRMR_0IN828_0IN300-MFG [mm]
  rrect5% 2.05x2.05 hole 1.35 paste-1000 mask+0: 1(-6.604,-1.943)
  round 2.05 hole 1.35 paste-1000 mask+0: 2(-6.147,1.943) 3(6.147,1.943) 4(6.604,-1.943)
  silkscreen extent -10.71,-4.62 10.71,4, body extent -10.82,-4.1 10.82,4.1, height 0.25
FP-RLTI-1379_PTH_XFRMR_0IN828_0IN300-MFG [mm]
  rrect5% 2.05x2.05 hole 1.35 paste-1000 mask+0: 1(-6.604,-1.943)
  round 2.05 hole 1.35 paste-1000 mask+0: 2(-6.147,1.943) 3(6.147,1.943) 4(6.604,-1.943)
  silkscreen extent -10.71,-4.62 10.71,4, body extent -10.82,-4.1 10.82,4.1, height 0.25
FP-SQ1431EH-T1_GE3_SC-70-MFG [mil]
  rrect25% 26x16 smd paste+0 mask+0: 1(-35,26) 2(-35,0) 3(-35,-26) 4(35,-26) 5(35,0) 6(35,26)
  silkscreen extent -84,19 -74,29, body extent -41,-39 41,39, height 43
FP-SSW-102-22-F-D-VS_RCPT4-MFG [mm]
  rrect8% 1.27x3.43 smd paste+0 mask+0: 1(1.27,-2.605) 2(1.27,2.605) 3(-1.27,-2.605) 4(-1.27,2.605)
  silkscreen extent -2.9,-5.11 2.9,2.54, body extent -3,-4.42 3,4.42, height 0.25
FP-SSW-104-22-F-D-VS-K_HDR8-MFG [mm]
  rrect8% 1.27x3.43 smd paste+0 mask+0: 1(3.81,-2.605) 2(3.81,2.605) 3(1.27,-2.605) 4(1.27,2.605) 5(-1.27,-2.605) 6(-1.27,2.605) 7(-3.81,-2.605) 8(-3.81,2.605)
  silkscreen extent -5.4,-5.04 5.4,2.54, body extent -5.5,-4.42 5.5,4.42, height 0.25
FP-TS40P05GHD2G_SIP4-MFG [mm]
  rrect4% 2.3x2.3 hole 1.5 paste-1000 mask+0: 1(-12.5,-0.75)
  round 2.3 hole 1.5 paste-1000 mask+0: 2(-2.5,-0.75) 3(5,-0.75) 4(12.5,-0.75)
  silkscreen extent -15.15,-3.65 15.15,2.4, body extent -15.25,-2.5 15.25,2.5, height 0.25
FP-US1MDFQ-13_D-FLAT-MFG [mm]
  rrect6% 1.85x1.7 smd: 1(-2.325,0) 2(2.325,0)
  silkscreen extent -3.95,-1.48 2.3,1.48, body extent -2.65,-1.3 2.65,1.3, height 1.1
FP-V20H510AUTO_RADIAL-MFG [mm]
  rrect6% 1.6x1.6 hole 1.05 paste-1000 mask+0: 1(-5,2)
  round 1.6 hole 1.05 paste-1000 mask+0: 2(5,-2)
  silkscreen extent -11.5,-3.65 11.5,3.65, body extent -11.6,-3.75 11.6,3.75, height 0.25
FP-VI-20173B_PTH_INDUCTOR_34MM00_19MM00-MFG [mm]
  rrect5% 4.75x1.85 hole 1.25 slot 4.15 at 0 deg paste-1000 mask+0: 1(16.05,-5.38)
  rrect100% 4.75x1.85 hole 1.25 slot 4.15 at 0 deg paste-1000 mask+0: 2(-16.05,-5.38)
  silkscreen extent -17.25,-10.5 19.12,10.5, body extent -18.52,-10.6 18.52,10.6, height 0.25
FP-VI-20174A_RADIAL-MFG [mm]
  rrect3% 3.35x3.35 hole 2.2 paste-1000 mask+0: 1(-9,-15)
  round 3.35 hole 2.2 paste-1000 mask+0: 2(-12.4,18) 3(9,15) 4(12.4,-18)
  silkscreen extent -25.9,-25.9 25.9,25.9, body extent -26,-26 26,26, height 0.25
FP-VT-20163_PTH_TRANSFORMER_73MM0_51MM0-MFG [mm]
  rrect5% 2.1x5.4 hole 4.8 slot 1.5 at 0 deg paste-1000 mask+0: 1(32.5,13)
  rrect100% 2.1x5.4 hole 4.8 slot 1.5 at 0 deg paste-1000 mask+0: 2(32.5,-13) 3(-37.5,-10) 4(-37.5,10)
  silkscreen extent -29.5,-30.5 34.62,30.5, body extent -41.37,-36.5 36.37,36.5, height 26.54
Harwin_S1621-46R [mm] "JUMPER TIN SMD"
  rect 2.4x2.8 smd: 1(-5.45,0) 2(5.45,0)
  silkscreen extent -7.05,-1.8 7.05,1.8, body extent -6.27,-1.15 6.28,1.15, height 1.8
IEC_HighVoltage_Small [mil]
  silkscreen extent -107,-88 107,97
IEC_HotSurface_Small [mil]
  silkscreen extent -107,-93 107,92
Keystone5000 [mil] "For Keystone 500x miniature loop terminals"
  round 80 hole 40: 1(0,0)
  silkscreen extent -52,-52 52,52, body extent -49,-49 49,49, height 182
Keystone5001 [mil] "For Keystone 500x miniature loop terminals"
  round 80 hole 40: 1(0,0)
  silkscreen extent -52,-52 52,52, body extent -49,-49 49,49, height 182
Label_650x200 [mil] "Thermal Transfer Label"
  round 1 on Mech13: 0(0,0)
  silkscreen extent -325,-100 325,100, body extent -325,-100 325,100, height 1
Mill-Max_851-43-008-10-001000 [mil] "Female Connector, 8x1, 1.27mm, Black, Tin, TH"
  rect 36x70 hole 26: 1(-175,0)
  oval 36x70 hole 26: 2(-125,0) 3(-75,0) 4(-25,0) 5(25,0) 6(75,0) 7(125,0) 8(175,0)
  silkscreen extent -231,-44 208,44, body extent -207,-43 208,44, height 161
Phoenix_1714955 [mm] "Terminal Block, 2x1, 6.35mm, TH"
  rect 1.8x1.8 hole 1.3: 1(-3.175,0)
  round 1.8 hole 1.3: 2(3.175,0)
  silkscreen extent -6.7,-7.9 6.35,4.6, body extent -6.92,-7.9 6.35,4.6, height 21.5
Phoenix_1714984 [mm] "Phoenix Contact"
  rect 1.8x1.8 hole 1.3 paste+0: 1(-9.52,1.65)
  round 1.8 hole 1.3 paste+0: 2(0,1.65) 3(9.52,1.65)
  silkscreen extent -14.85,-6.81 14.28,6.25, body extent -14.85,-6.25 14.28,6.25, height 21.51
PW0014A_N [mm] "TSOP, 14-Leads, Body 5x4.4mm, Pitch 0.65mm, IPC Medium Density"
  oval 1.4x0.45 smd: 1(-2.95,1.95) 2(-2.95,1.3) 3(-2.95,0.65) 4(-2.95,0) 5(-2.95,-0.65) 6(-2.95,-1.3) 7(-2.95,-1.95) 8(2.95,-1.95) 9(2.95,-1.3) 10(2.95,-0.65) 11(2.95,0) 12(2.95,0.65) 13(2.95,1.3) 14(2.95,1.95)
  silkscreen extent -3.4,-2.55 1.85,2.55, body extent -3.21,-2.5 3.21,2.5, height 1
RQS0052A-MFG [mm]
  rrect10% 1.05x1.05 smd paste+0 mask+0: 1(-5.675,5.2) 16(-5.675,-5.2) 27(5.675,-5.2) 42(5.675,5.2)
  rrect25% 1.05x0.4 smd paste+0 mask+0: 2(-5.675,4.225) 3(-5.675,3.575) 4(-5.675,2.925) 5(-5.675,2.275) 6(-5.675,1.625) 7(-5.675,0.975) 8(-5.675,0.325) 9(-5.675,-0.325) 10(-5.675,-0.975) 11(-5.675,-1.625) 12(-5.675,-2.275) 13(-5.675,-2.925) 14(-5.675,-3.575) 15(-5.675,-4.225) 28(5.675,-4.225) 29(5.675,-3.575) 30(5.675,-2.925) 31(5.675,-2.275) 32(5.675,-1.625) 33(5.675,-0.975) 34(5.675,-0.325) 35(5.675,0.325) 36(5.675,0.975) 37(5.675,1.625) 38(5.675,2.275) 39(5.675,2.925) 40(5.675,3.575) 41(5.675,4.225)
  rrect25% 0.4x1.05 smd paste+0 mask+0: 17(-1.935,-5.675) 18(-1.285,-5.675) 19(-0.635,-5.675) 20(0.015,-5.675) 21(0.665,-5.675) 22(1.315,-5.675) 23(1.965,-5.675) 24(2.615,-5.675) 25(3.265,-5.675) 26(3.915,-5.675) 43(3.915,5.675) 44(3.265,5.675) 45(2.615,5.675) 46(1.965,5.675) 47(1.315,5.675) 48(0.665,5.675) 49(0.015,5.675) 50(-0.635,5.675) 51(-1.285,5.675) 52(-1.935,5.675)
  silkscreen extent -6.88,-6.05 4.77,6.05, body extent -6,-6 6,6, height 1
RSV0016A-MFG [mm]
  rrect50% 0.7x0.2 smd: 1(-0.75,0.6)
  rrect50% 0.6x0.2 smd: 2(-0.8,0.2) 3(-0.8,-0.2) 4(-0.8,-0.6) 9(0.8,-0.6) 10(0.8,-0.2) 11(0.8,0.2) 12(0.8,0.6)
  rrect50% 0.2x0.6 smd: 5(-0.6,-1.2) 6(-0.2,-1.2) 7(0.2,-1.2) 8(0.6,-1.2) 13(0.6,1.2) 14(0.2,1.2) 15(-0.2,1.2) 16(-0.6,1.2)
  silkscreen extent -1.9,-1.68 1.28,1.68, body extent -0.9,-1.3 0.9,1.3, height 0.55
SAMTEC_SSW-103-22-F-D-VS-K [mil] "Samtec"
  rect 40x120 smd: 1(-100.01,109.99) 2(-100.01,-110.01) 3(-0.01,109.99) 4(-0.01,-110.01) 5(99.99,109.99) 6(99.99,-110.01)
  silkscreen extent -168,-179 167,179, body extent -160,-155 160,155, height 390
Samtec_TFM-106-02-x-D-A [mm] "Header(Shrouded), 1.27mm, 6x2, SMT"
  rect 2.92x0.74 smd: 1(-1.715,3.175) 2(1.715,3.175) 3(-1.715,1.905) 4(1.715,1.905) 5(-1.715,0.635) 6(1.715,0.635) 7(-1.715,-0.635) 8(1.715,-0.635) 9(-1.715,-1.905) 10(1.715,-1.905) 11(-1.715,-3.175) 12(1.715,-3.175)
  round 0 hole 1.42 unplated: MH1(0,4.765) MH2(0,-4.765)
  silkscreen extent -3.2,-5.4 2.86,5.4, body extent -2.98,-5.4 2.98,5.4, height 5.74
SOD-123 [mm] "On Semi recommended land pattern"
  rect 0.915x1.22 smd: 1(-1.637,0) 2(1.637,0)
  silkscreen extent -2.74,-1.17 2.03,1.17, body extent -1.93,-0.9 1.93,0.9, height 1.35
SOD-323 [mm] "NXP recommended land pattern"
  rect 0.6x0.6 smd: 1(-1.1,0) 2(1.1,0)
  silkscreen extent -2.06,-0.86 1.53,0.86, body extent -1.3,-0.67 1.3,0.68, height 1.1
SOT-23 [mm] "SOT23, 3-Leads, Body 2.9x1.3mm, Pitch 0.95mm, Lead Span 2.5mm, IPC Medium Density"
  rrect50% 1x0.6 smd: 1(-1.2,0.95) 2(-1.2,-0.95) 3(1.2,0)
  silkscreen extent -1.63,-1.5 0.7,1.5, body extent -1.16,-1.45 1.21,1.45, height 1
SOT-23L [mm] "SOT23, 3-Leads, Body 2.9x1.3mm, Pitch 0.95mm, Lead Span 2.5mm, IPC High Density"
  rrect50% 0.8x0.6 smd: 1(-1.1,0.95) 2(-1.1,-0.95) 3(1.1,0)
  silkscreen extent -1.5,-1.5 0.7,1.5, body extent -1.16,-1.45 1.21,1.45, height 1
SOT-223 [mm] "SOT223/SC73, 4-Leads, Body 6.5x3.5mm, Pitch 2.3mm, Lead Span 7mm, IPC Medium Density"
  rrect10% 2.4x1 smd: 1(-2.9,2.3) 2(-2.9,0) 3(-2.9,-2.3)
  rrect4% 2.4x3.3 smd: 4(2.9,0)
  silkscreen extent -3.32,-3.35 1.4,3.35, body extent -3.5,-3.25 3.5,3.25, height 1.62
SRN3015TA [mm] "SMD, 2-Leads, Body 3x3mm"
  rect 1.1x3.2 smd: 1(-1.05,0) 2(1.05,0)
  silkscreen extent -0.2,-1.5 0.22,1.5, body extent -1.5,-1.52 1.5,1.52, height 1.48
Sullins_GRPB041VWVN-RC [mm] "TH, Header, 1.27 mm, 4x1, Straight"
  rect 1.05x1.05 hole 0.75: 1(-1.905,0)
  round 1.05 hole 0.75: 2(-0.635,0) 3(0.635,0) 4(1.905,0)
  silkscreen extent -3.54,-1.07 2.79,1.07, body extent -2.79,-1.07 2.79,1.07, height 4.3
TE_282856-2 [mm] "TH, 2-Leads, Body 10x10mm, Pitch 5mm"
  rect 1.9x1.9 hole 1.4: 1(-2.5,0)
  round 1.9 hole 1.4: 2(2.5,0)
  silkscreen extent -5.61,-5 5.5,5, body extent -5,-5 5.5,5, height 19
TE_282856-3 [mm] "Receptacle, 3x1, 5mm, R/A, TH"
  rect 1.9x1.9 hole 1.4: 1(-5,0)
  round 1.9 hole 1.4: 2(0,0) 3(5,0)
  silkscreen extent -8,-5 8,5, body extent -7.5,-5 8,5, height 19
TI_Stacked_Overlay_Small [mil]
  silkscreen extent -418,-98 418,98
WEEE_Minimum [mil] "WEEElie bin"
  silkscreen extent -95,-172 99,104

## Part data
C1 C255: library part CMP-0009587-2, "CAP, CERM, 2200 pF, 300 V, +/- 20%, Y5U, AEC-Q200 Grade 1, D9.5xT5mm", Cap_Case=9.5x5mm, Manufacturer=Vishay-Bccomponents, Supplier Part Number 1=BC2914-ND, TempCo=Y5U, Tolerance_%=20%, Value1=Unknown, Value2=300V, ValueDisplayed=2200pF
C2 C3 C4 C5 C6 C7 C8 C9 C10 C11 C12 C13 C14 C15 C16 C17: library part CMP-0090696-1, "0.033µF ±5% 630V Ceramic Capacitor C0G, NP0 1210 (3225 Metric)", Digikey Part Number=399-20933-1-ND, Manufacturer=Kemet, Mouser Part Number=80-C1210X333JBGAUTO, Operating Temperature Range="-55°C to +125°C", TempCo=30ppm/°C, Temperature Characteristic=C0G, Tolerance_%=5%, ValueDisplayed=0.033uF
C18 C20: library part CMP-0090464-1, "300µF 500V Aluminum Electrolytic Capacitors Radial, Can - Snap-In 687.4mOhm @ 100Hz 7000 Hrs @ 105°C", Digikey Part Number=399-17946-ND, Leakage Current=450uA, Manufacturer=Kemet, Mouser Part Number=80-ALA8DA301CF500, Operating Temperature Range="-40°C to +105°C", Tolerance_%=20%, ValueDisplayed=300uF
C19 C21: library part CMP-0009311-2, "CAP, CERM, 1 uF, 500 V, +/- 20%, B58031, AEC-Q200 Grade 0, 6.84x7.85mm", Cap_Case=10.84x7.85x4.5mm, Manufacturer=TDK, PartNumber=B58031I5105M062, TempCo=B58031, Tolerance_%=20%, Value1=Unknown, Value2=500V, ValueDisplayed=1uF
C22 C24 C25 C26 C33 C34 C35 C126 C129 C133 C136 C137 C139 C140 C142 C143 C144 C145 C205 C206 C212 C236 C239 C244 C249 C251 C252 C253 C254: library part CMP-0080610-1, "CAP, CERM, 0.1 µF, 25 V,+/- 10%, X7R, AEC-Q200 Grade 1, 0402", Cap_Case=0402, Manufacturer=TDK, Supplier Part Number 1=445-6902-1-ND, TempCo=X7R, Tolerance_%=10%, Value2=25V, ValueDisplayed=0.1µF
C23: library part CMP-0006353-2, "CAP, CERM, 0.022 uF, 25 V, +/- 10%, X7R, AEC-Q200 Grade 1, 0402", Cap_Case=0402, Manufacturer=MuRata, Supplier Part Number 1=490-6044-1-ND, TempCo=X7R, Tolerance_%=10%, Value1=Unknown, Value2=25V, ValueDisplayed=0.022uF
C27 C28 C29 C30 C37 C132 C134 C202 C203 C209: library part CMP-0080702-1, "CAP, CERM, 0.1 µF, 16 V,+/- 5%, X7R, AEC-Q200 Grade 1, 0402", Cap_Case=0402, Manufacturer=MuRata, Supplier Part Number 1=490-16433-1-ND, TempCo=X7R, Tolerance_%=5%, Value2=16V, ValueDisplayed=0.1µF
C31: library part CMP-0081062-1, "CAP, CERM, 10 µF, 25 V,+/- 5%, X7R, AEC-Q200 Grade 1, 1206", Cap_Case=1206_180, Manufacturer=Kemet, Supplier Part Number 1=399-15734-1-ND, TempCo=X7R, Tolerance_%=5%, Value2=25V, ValueDisplayed=10µF
C32: library part CMP-0009012-3, "CAP, CERM, 22 uF, 10 V, +/- 10%, X6S, AEC-Q200 Grade 2, 1206", Cap_Case=1206, Manufacturer=MuRata, Supplier Part Number 1=490-12405-1-ND, TempCo=X6S, Tolerance_%=10%, Value1=Unknown, Value2=10V, ValueDisplayed=22uF
C36: library part CMP-0082523-1, "CAP, CERM, 1 µF, 25 V,+/- 10%, X7R, AEC-Q200 Grade 1, 0603", Cap_Case=0603, Manufacturer=TDK, Supplier Part Number 1=445-9819-1-ND, TempCo=X7R, Tolerance_%=10%, Value2=25V, ValueDisplayed=1µF
C38 C53 C60 C75 C82 C97 C104 C119 C146 C161 C168 C183: library part CMP-0007975-2, "CAP, CERM, 2.2 uF, 25 V, +/- 10%, X7R, AEC-Q200 Grade 1, 0805", Cap_Case=0805, Manufacturer=TDK, Supplier Part Number 1=445-6965-1-ND, TempCo=X7R, Tolerance_%=10%, Value1=Unknown, Value2=25V, ValueDisplayed=2.2uF
C39 C54 C61 C76 C83 C98 C105 C120 C147 C162 C169 C184: library part CMP-0750099-1, "CAP, CERM, 1 µF, 35 V,+/- 10%, X5R, AEC-Q200 Grade 3, 0402", Cap_Case=0402, Manufacturer=MuRata, TempCo=X5R, Tolerance_%=10%, Value2=35V, ValueDisplayed=1µF
C40 C55 C62 C77 C84 C99 C106 C121 C148 C163 C170 C185: library part CMP-0006356-2, "CAP, CERM, 0.1 uF, 50 V, +/- 10%, X7R, AEC-Q200 Grade 1, 0402", Cap_Case=0402, Manufacturer=MuRata, Supplier Part Number 1=490-10672-1-ND, TempCo=X7R, Tolerance_%=10%, Value1=Unknown, Value2=50V, ValueDisplayed=0.1uF
C41 C56 C63 C78 C85 C100 C107 C122 C149 C164 C171 C186: library part CMP-0090521-1, "68pF ±5% 50V Ceramic Capacitor C0G, NP0 0402 (1005 Metric)", Digikey Part Number=490-12653-1-ND, Manufacturer=Murata, Mouser Part Number=81-GCM1555C1H680JA6D, Operating Temperature Range="-55°C to +125°C", TempCo=30ppm/°C, Temperature Characteristic=C0G, Tolerance_%=5%, ValueDisplayed=68pF
C42 C57 C64 C79 C86 C101 C108 C123 C150 C165 C172 C187: library part CMP-0006348-2, "CAP, CERM, 22 pF, 50 V, +/- 5%, C0G/NP0, AEC-Q200 Grade 1, 0402", Cap_Case=0402, Manufacturer=MuRata, Supplier Part Number 1=490-9648-1-ND, TempCo=C0G/NP0, Tolerance_%=5%, Value1=Unknown, Value2=50V, ValueDisplayed=22pF
C43 C58 C65 C80 C87 C102 C109 C124 C151 C166 C173 C188: library part CMP-0078265-1, "CAP, CERM, 0.22 µF, 16 V,+/- 10%, X7R, AEC-Q200 Grade 1, 0402", Cap_Case=0402, Manufacturer=MuRata, Supplier Part Number 1=490-10671-1-ND, TempCo=X7R, Tolerance_%=10%, Value2=16V, ValueDisplayed=0.22µF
